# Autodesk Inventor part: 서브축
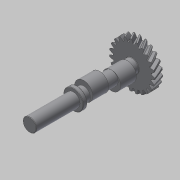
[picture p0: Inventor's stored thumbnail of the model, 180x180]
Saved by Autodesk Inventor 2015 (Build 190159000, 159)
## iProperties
Created: 2016-12
Part Number: 서브축
Material: 강철, 탄소
Document SubType Name: Modeling
Designer: mduedu
Categories: <?xml version="1.0" encoding="UTF-16"?> <MemberInstance><Categories><FamilyTemplate><FamilyTemplateParameter ValueType="xs:double" Id="1" ObjectReferenceKey="da
Density: 7.87 g/cm^3
Mass: 484.101 g
Surface Area: 171.575 cm^2
Volume: 61.5122 cm^3
Appearance: 기본값
CustomPartVersion: 1
Author: mduedu
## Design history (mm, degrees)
sketch "Sketch1"
  geometry: C1 r 28.558 at (0, 0)
  constraints: 1 centre point
  dimensions: "d0" = 57.11622 diameter of C1 (= da_da)
extrude "Extrusion1" new body sketch "Sketch1" distance "d1" = 10 (= da_b); taper "d2" = 0 deg
workplane "Work Plane2"
sketch "Sketch2"
  geometry: C1 r 28.558 at (0, 0) reference; C2 r 26.558 at (0, 0)
  constraints: 1 centre point, 1 coincident
  dimensions: "d3" = 53.11622 diameter of C2 (= da_dw)
feature "피치 지름" sketch "Sketch2" dims "d4" = 10, "d5" = 0
workplane "Work Plane8"
workplane "Work Plane9"
feature "스퍼 기어" dims "da_b" = 10, "da_d" = 53.11622, "da_aw" = 43.87862, "da_da" = 57.11622, "da_df" = 48.11622, "da_dw" = 53.11622, angle "da_beta" = 30 deg, "da_lefttooth" = 10, "da_righttooth" = 0
sketch "스케치3"
  geometry: C1 r 12.5 at (0, 0); 1 further point
  constraints: 1 centre point, 1 coincident
  dimensions: "d49" = 25 diameter of C1
extrude "돌출2" join sketch "스케치3" distance "d50" = 6; taper "d51" = 0 deg
sketch "스케치4"
  geometry: C1 r 8.5 at (0, 0); 1 further point
  constraints: 1 centre point, 1 coincident
  dimensions: "d52" = 17 diameter of C1
extrude "돌출3" join sketch "스케치4" distance "d53" = 123; taper "d54" = 0 deg
sketch "스케치5"
  geometry: C1 r 7.5 at (0, 0); 1 further point
  constraints: 1 centre point, 1 coincident
  dimensions: "d55" = 15 diameter of C1
extrude "돌출4" join sketch "스케치5" distance "d56" = 6; taper "d57" = 0 deg
sketch "스케치6"
  geometry: C1 r 4 at (0, 0); 1 further point
  constraints: 1 centre point, 1 coincident
  dimensions: "d58" = 8 diameter of C1
extrude "돌출5" join sketch "스케치6" distance "d59" = 7; taper "d60" = 0 deg
chamfer "모따기1" distance "d61" = 0.5; stored, may be unused: second distance "d62" = 2, angle "d63" = 45 deg
fillet "모깎기1" dims "d64" = 0.5
node "작업 평면11"
sketch "스케치7"
  geometry: C1 r 11.5 at (0, 3); C2 r 8.5 at (0, 0) reference; 1 further point
  constraints: 1 centre point, 1 tangent, 1 vertical alignment
  dimensions: "d66" = 3 distance of point (0, 0) C1.centre; "d67" = 23 diameter of C1 (derived)
extrude "돌출6" join sketch "스케치7" stored distance "d68" = 20; taper "d69" = 0 deg
node "작업 평면13"
sketch "스케치9"
  geometry: C1 r 11.5 at (0, -3); C2 r 8.5 at (0, 0) reference; 1 further point
  constraints: 1 centre point, 1 tangent, 1 vertical alignment
  dimensions: "d78" = 3 distance of C1.centre point (0, 0); "d79" = 23 diameter of C1 (derived)
extrude "돌출8" join sketch "스케치9" stored distance "d80" = 20; taper "d81" = 0 deg
node "작업 평면12"
sketch "스케치8"
  geometry: C1 r 12.5 at (0, 0) reference; 1 further point
extrude "돌출7" join sketch "스케치8" distance "d71" = 5; taper "d72" = 0 deg
chamfer "모따기2" distance "d73" = 0.5; stored, may be unused: second distance "d74" = 2, angle "d75" = 45 deg
sketch "스케치10"
  geometry: C1 r 12.5 at (0, 0) reference; C2 r 8.5 at (0, 0) reference; 1 further point
extrude "돌출9" cut sketch "스케치10" stored distance "d82" = 20; taper "d83" = 0 deg
fillet "모깎기2" dims "d84" = 0.5
body "Solid1"
body "Srf1"
other parameters: "d16" = 43.87862 (= da_aw), "d17" = 0, "d34" = 1.36591 (computed from da_z), "d39" = 0, "d41" = 0, "d43" = 43.87862 (= da_aw), "d46" = 43.87862 (= da_aw), "d47" = 0, "d48" = 0, "d65" = 45, "d70" = 68, "d76" = -35
